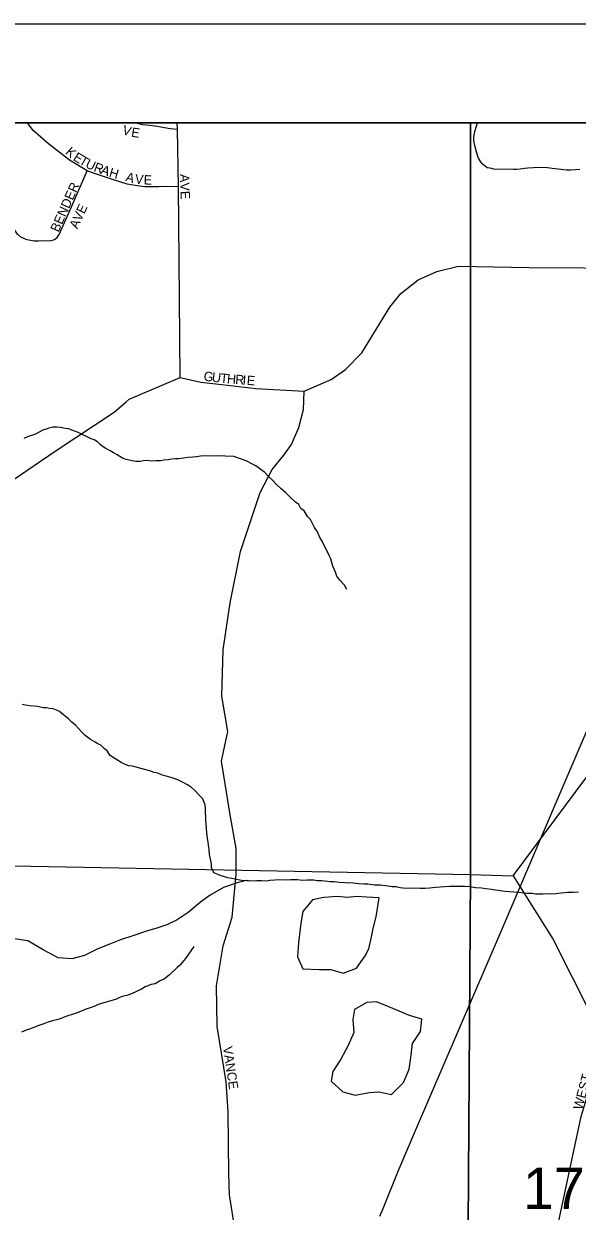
# Model space of a CAD drawing. Extents: x -209 to 4852, y 0 to 905.
# Drawn here: x 494.13 to 505.3, y 316.6 to 340.56 of the extents above; entities that cross this region are included whole.
import ezdxf

# ---------------------------------------------------------------- set-up
doc = ezdxf.new("R2010")
doc.units = 0
for name, color, linetype in [('Default', 7, 'Continuous'), ('GM_X_Airport_Location_Class_2', 7, 'Continuous'), ('GM_X_Airport_Location_Class_3', 7, 'Continuous'), ('GM_X_County_Road', 7, 'Continuous'), ('GM_X_Major_River', 7, 'Continuous'), ('GM_X_Minor_Lake_Text', 7, 'Continuous'), ('GM_X_Minor_River', 7, 'Continuous'), ('GM_X_Township_Road_Text', 7, 'Continuous'), ('GM_X_US_Location', 7, 'Continuous'), ('GM_X_US_Route', 7, 'Continuous'), ('SH_Data', 7, 'Continuous')]:
    doc.layers.add(name, color=color, linetype=linetype)

msp = doc.modelspace()

# ---------------------------------------------------------------- linework, layer by layer
at = {"layer": 'Default'}
msp.add_lwpolyline([(571.768, 202.559), (571.768, 338.559), (435.768, 338.559), (435.768, 202.559)], close=True, dxfattribs=at)
at = {"layer": 'GM_X_Airport_Location_Class_2'}
for points in [[(494.16, 336.213), (494.067, 336.252), (494.003, 336.316), (493.899, 336.464), (493.805, 336.75), (493.677, 337.045), (493.559, 337.213), (492.909, 338.08), (492.597, 338.559)], [(495.514, 337.552), (495.408, 337.589), (495.05, 337.81), (494.623, 338.137), (494.318, 338.404), (494.205, 338.559)], [(497.227, 338.429), (497.084, 338.438), (496.965, 338.459), (496.82, 338.485), (496.67, 338.505), (496.525, 338.521), (496.362, 338.559)], [(497.286, 333.423), (497.273, 335.023), (497.25, 337.271), (497.227, 338.429), (497.226, 338.559)], [(494.841, 336.307), (495.088, 336.865), (495.408, 337.589)], [(497.25, 337.271), (497.008, 337.277), (496.855, 337.269), (496.665, 337.269), (496.573, 337.269), (496.413, 337.292), (496.215, 337.322), (495.918, 337.414), (495.514, 337.552)], [(494.16, 336.213), (494.339, 336.181), (494.425, 336.181), (494.526, 336.184), (494.657, 336.181), (494.748, 336.209), (494.803, 336.244), (494.841, 336.307)], [(499.786, 333.145), (499.786, 333.145), (500.334, 333.382), (500.624, 333.587), (500.947, 333.923), (501.514, 334.839), (501.736, 335.116), (502.086, 335.394), (502.464, 335.564), (502.903, 335.668), (504.329, 335.64), (506.529, 335.63), (506.737, 335.574), (506.888, 335.489), (507.148, 335.253), (507.852, 334.299), (507.902, 334.336)], [(496.191, 332.931), (496.254, 332.986), (496.651, 333.156), (497.286, 333.423)], [(497.286, 333.423), (497.701, 333.331), (498.123, 333.279), (498.812, 333.204), (499.786, 333.145)], [(498.395, 316.207), (498.277, 316.932), (498.263, 317.361), (498.251, 318.606), (498.211, 319.213), (498.033, 320.331), (498.019, 321.152), (498.151, 321.956), (498.336, 322.536), (498.413, 323.401), (498.413, 323.923), (498.283, 324.64), (498.12, 325.684), (498.244, 326.281), (498.125, 326.993), (498.151, 327.93), (498.296, 328.879), (498.501, 329.914), (498.896, 331.101), (499.14, 331.569), (499.378, 331.853), (499.529, 332.07), (499.681, 332.413), (499.773, 332.776), (499.786, 333.145)], [(483.392, 325.722), (489.662, 325.638), (489.945, 325.638), (490.059, 325.714), (490.153, 325.846), (490.191, 326.111), (490.153, 327.49), (490.172, 327.546), (490.172, 327.565), (490.191, 327.678), (490.267, 327.811), (490.474, 328.037), (491.74, 328.906), (492.477, 329.378), (492.722, 329.548), (492.911, 329.737), (493.005, 329.926), (493.194, 330.455), (493.326, 330.814), (493.326, 330.833), (493.61, 331.154), (494.781, 331.947), (495.952, 332.722), (496.191, 332.931)], [(503.856, 313.234), (504.046, 313.362), (504.197, 313.663), (504.53, 314.568), (504.788, 315.633), (504.917, 316.375), (505.38, 318.516), (505.961, 320.453), (506.267, 321.322), (506.357, 321.685), (506.469, 322.321), (506.657, 323.59), (507.46, 326.374), (508.038, 328.172), (508.092, 328.334)]]:
    msp.add_lwpolyline(points, dxfattribs=at)
at = {"layer": 'GM_X_County_Road'}
for points in [[(505.349, 337.621), (505.265, 337.615), (505.166, 337.602), (505.082, 337.605), (504.916, 337.624), (504.794, 337.642), (504.696, 337.652), (504.521, 337.656), (504.414, 337.651), (504.3, 337.647), (504.231, 337.641), (504.147, 337.628), (504.071, 337.622), (504.01, 337.616), (503.615, 337.626), (503.539, 337.643), (503.479, 337.652), (503.382, 337.73), (503.338, 337.792), (503.301, 337.861), (503.266, 337.976), (503.231, 338.106), (503.211, 338.198), (503.213, 338.274), (503.231, 338.388), (503.287, 338.559)], [(500.645, 329.147), (500.602, 329.232), (500.506, 329.333), (500.447, 329.418), (500.418, 329.495), (500.368, 329.617), (500.326, 329.763), (500.29, 329.832), (500.239, 329.948), (500.195, 330.017), (500.152, 330.124), (500.101, 330.194), (500.058, 330.309), (499.992, 330.395), (499.912, 330.556), (499.853, 330.618), (499.787, 330.734), (499.72, 330.781), (499.676, 330.858), (499.609, 330.906), (499.505, 331.007), (499.408, 331.101), (499.319, 331.179), (499.23, 331.265), (499.148, 331.35), (499.074, 331.421), (498.992, 331.506), (498.917, 331.561), (498.813, 331.64), (498.745, 331.672), (498.618, 331.744), (498.52, 331.776), (498.369, 331.826), (498.194, 331.838), (498.034, 331.842), (497.928, 331.837), (497.791, 331.84), (497.692, 331.835), (497.616, 331.822), (497.539, 331.816), (497.44, 331.811), (497.349, 331.798), (497.25, 331.785), (497.189, 331.779), (497.112, 331.773), (497.044, 331.76), (496.952, 331.754), (496.891, 331.741), (496.8, 331.743), (496.708, 331.738), (496.617, 331.747), (496.541, 331.742), (496.48, 331.728), (496.389, 331.73), (496.283, 331.748), (496.192, 331.766), (496.117, 331.798), (496.012, 331.861), (495.937, 331.901), (495.869, 331.941), (495.772, 331.996), (495.675, 332.067), (495.615, 332.122), (495.548, 332.162), (495.487, 332.186), (495.382, 332.242), (495.292, 332.282), (495.209, 332.322), (495.096, 332.363), (495.036, 332.387), (494.968, 332.396), (494.869, 332.414), (494.793, 332.423), (494.717, 332.418), (494.656, 332.404), (494.579, 332.383), (494.51, 332.362), (494.426, 332.311), (494.364, 332.282), (494.303, 332.261), (494.203, 332.225), (494.126, 332.189)], [(498.243, 323.33), (498.092, 323.379), (498.032, 323.403), (497.964, 323.428), (497.914, 323.536), (497.915, 323.604), (497.902, 323.68), (497.875, 323.803), (497.87, 323.902), (497.856, 323.986), (497.85, 324.054), (497.837, 324.123), (497.825, 324.237), (497.812, 324.329), (497.806, 324.42), (497.8, 324.489), (497.802, 324.565), (497.796, 324.626), (497.798, 324.724), (497.785, 324.793), (497.743, 324.923), (497.683, 324.986), (497.572, 325.095), (497.512, 325.15), (497.43, 325.205), (497.332, 325.26), (497.235, 325.309), (497.144, 325.341), (497.076, 325.358), (497.001, 325.383), (496.91, 325.408), (496.835, 325.44), (496.759, 325.457), (496.669, 325.49), (496.518, 325.531), (496.397, 325.565), (496.314, 325.582), (496.245, 325.591), (496.163, 325.624), (496.095, 325.656), (496.02, 325.703), (495.952, 325.743), (495.863, 325.806), (495.819, 325.883), (495.759, 325.93), (495.685, 326.008), (495.625, 326.032), (495.565, 326.064), (495.475, 326.12), (495.363, 326.199), (495.296, 326.269), (495.229, 326.339), (495.17, 326.409), (495.096, 326.471), (495.029, 326.534), (494.932, 326.62), (494.85, 326.683), (494.79, 326.714), (494.722, 326.739), (494.646, 326.748), (494.578, 326.758), (494.517, 326.759), (494.404, 326.785), (494.252, 326.796), (494.161, 326.814), (494.093, 326.823)], [(498.713, 323.265), (498.625, 323.275), (498.434, 323.225), (498.159, 323.132), (497.891, 322.977), (497.691, 322.837), (497.444, 322.629), (497.221, 322.481), (497.014, 322.379), (496.815, 322.314), (496.602, 322.25), (496.35, 322.163), (496.082, 322.077), (495.876, 321.998), (495.624, 321.896), (495.356, 321.764), (495.096, 321.693), (494.823, 321.714), (494.516, 321.879), (494.208, 322.06), (493.943, 322.096)], [(505.325, 323.041), (505.218, 323.036), (505.104, 323.031), (505.043, 323.025), (504.975, 323.019), (504.875, 323.006), (504.784, 323.001), (504.7, 323.003), (504.601, 322.998), (504.525, 323), (504.457, 323.001), (504.389, 323.011), (504.282, 323.013), (504.214, 323.023), (504.123, 323.032), (504.017, 323.043), (503.842, 323.055), (503.751, 323.064), (503.645, 323.082), (503.569, 323.092), (503.456, 323.11), (503.365, 323.12), (503.243, 323.13), (503.137, 323.148), (503.023, 323.151), (502.917, 323.153), (502.818, 323.156), (502.726, 323.151), (502.429, 323.135), (502.323, 323.123), (502.224, 323.117), (502.132, 323.112), (501.783, 323.121), (501.722, 323.13), (501.646, 323.147), (501.563, 323.149), (501.479, 323.159), (501.32, 323.178), (501.206, 323.181), (501.07, 323.199), (500.994, 323.201), (500.88, 323.211), (500.773, 323.222), (500.614, 323.226), (500.492, 323.236), (500.401, 323.246), (500.31, 323.248), (500.204, 323.259), (500.136, 323.268), (500.052, 323.27), (499.984, 323.279), (499.855, 323.282), (499.756, 323.277), (499.649, 323.287), (499.513, 323.291), (499.452, 323.285), (499.292, 323.289), (499.094, 323.278), (499.025, 323.265), (498.926, 323.267), (498.828, 323.27), (498.713, 323.265), (498.63, 323.267), (498.531, 323.277), (498.448, 323.287), (498.387, 323.303), (498.327, 323.313), (498.243, 323.33)], [(497.295, 321.582), (497.395, 321.702), (497.567, 321.942)], [(497.295, 321.582), (497.225, 321.523), (497.062, 321.367), (496.969, 321.294), (496.869, 321.243), (496.776, 321.192), (496.7, 321.179), (496.577, 321.128), (496.5, 321.085), (496.3, 320.991), (496.207, 320.955), (496.139, 320.942), (496.062, 320.913), (496, 320.884), (495.632, 320.772), (495.563, 320.743), (495.487, 320.714), (495.387, 320.679), (495.302, 320.643), (495.225, 320.614), (495.103, 320.572), (495.018, 320.543), (494.942, 320.515), (494.88, 320.494), (494.796, 320.465), (494.704, 320.445), (494.597, 320.409), (494.535, 320.381), (494.428, 320.353), (494.313, 320.302), (494.243, 320.274), (494.175, 320.253), (494.082, 320.217)]]:
    msp.add_lwpolyline(points, dxfattribs=at)
at = {"layer": 'GM_X_Major_River'}
for points in [[(501.297, 322.927), (501.046, 322.939), (500.849, 322.95), (500.659, 322.931), (500.462, 322.95), (500.181, 322.933), (499.953, 322.884), (499.758, 322.652), (499.724, 322.455), (499.698, 322.25), (499.67, 322.015), (499.65, 321.734), (499.759, 321.496), (500.092, 321.482), (500.327, 321.478), (500.576, 321.404), (500.844, 321.506), (501.016, 321.753)], [(501.016, 321.753), (501.094, 321.896), (501.136, 322.108), (501.178, 322.305), (501.243, 322.54), (501.297, 322.927)], [(501.496, 320.725), (501.248, 320.829), (501.051, 320.817), (500.805, 320.67), (500.771, 320.473), (500.788, 320.206), (500.677, 319.95), (500.527, 319.672), (500.363, 319.424), (500.329, 319.227), (500.568, 319.009), (500.817, 318.943), (501.106, 318.999), (501.296, 319.01), (501.546, 318.96), (501.793, 319.198), (501.905, 319.47)], [(501.905, 319.47), (501.939, 319.705), (501.975, 319.986), (502.132, 320.226), (502.159, 320.476), (501.91, 320.55), (501.496, 320.725)]]:
    msp.add_lwpolyline(points, dxfattribs=at)
at = {"layer": 'GM_X_Minor_Lake_Text'}
msp.add_lwpolyline([(514.904, 338.559), (483.334, 338.559), (483.392, 325.723), (483.369, 322.855), (483.249, 313.713), (483.171, 310.029), (483.074, 303.486), (482.984, 295.952), (482.84, 285.356)], dxfattribs=at)
at = {"layer": 'GM_X_Minor_River'}
for points in [[(503.146, 338.559), (483.207, 338.559), (483.256, 323.774), (503.144, 323.396)], [(514.348, 338.559), (503.146, 338.559), (503.144, 323.396), (504.007, 323.372), (505.686, 325.628), (507.263, 328.166), (508.201, 330.11), (509.524, 332.419), (511.394, 334.77), (513.318, 336.779)], [(483.256, 323.774), (503.144, 323.396), (503.056, 310.202), (502.765, 309.61), (502.156, 308.265), (501.547, 306.481), (500.992, 304.719), (500.816, 303.404), (483.023, 303.524), (483.246, 322.903)], [(503.144, 323.396), (504.007, 323.372), (504.809, 322.084), (505.956, 319.821), (506.865, 318.236), (506.647, 316.293), (506.296, 314.944), (505.386, 313.673), (504.418, 312.131), (503.056, 310.202)]]:
    msp.add_lwpolyline(points, close=True, dxfattribs=at)
at = {"layer": 'GM_X_US_Location'}
msp.add_lwpolyline([(515.21, 338.559), (475.437, 338.559)], dxfattribs=at)
msp.add_lwpolyline([(515.21, 338.559), (475.437, 338.559)], dxfattribs=at)
at = {"layer": 'GM_X_US_Route'}
msp.add_lwpolyline([(501.317, 316.503), (501.379, 316.657), (501.686, 317.412), (502.031, 318.229), (503.771, 322.27), (504.93, 324.99), (506.153, 327.828)], dxfattribs=at)
at = {"layer": 'SH_Data'}
for p, q in [((433.768, 340.559), (573.768, 340.559)), ((435.768, 338.559), (571.768, 338.559))]:
    msp.add_line(p, q, dxfattribs=at)

# ---------------------------------------------------------------- texts
at = {"layer": 'GM_X_Airport_Location_Class_3'}
for s, height, rotation, p in [('V', 0.189, 343.6244, (496.102, 338.336)), ('E', 0.189, 350.8438, (496.287, 338.283)), ('K', 0.189, 318.0307, (494.955, 337.951)), ('E', 0.189, 328.3974, (495.109, 337.817)), ('T', 0.189, 329.7623, (495.227, 337.744)), ('U', 0.189, 334.5434, (495.357, 337.669)), ('R', 0.189, 339.915, (495.526, 337.59)), ('A', 0.189, 339.9693, (495.667, 337.538)), ('H', 0.189, 343.6244, (495.836, 337.477)), ('A', 0.189, 344.3519, (496.17, 337.389)), ('BENDER', 0.1894, 66.1408, (494.829, 336.341)), ('V', 0.189, 353.5709, (496.363, 337.338)), ('E', 0.189, 358.1599, (496.545, 337.318)), ('A', 0.189, 270.1093, (497.28, 337.527)), ('V', 0.189, 272.0332, (497.281, 337.353)), ('E', 0.189, 273.7302, (497.287, 337.181)), ('E', 0.189, 64.3147, (495.347, 336.71)), ('V', 0.189, 65.4294, (495.278, 336.56)), ('A', 0.189, 65.7423, (495.209, 336.408)), ('G', 0.189, 352.6148, (497.749, 333.362)), ('U', 0.189, 352.7454, (497.915, 333.341)), ('T', 0.189, 354.3645, (498.086, 333.319)), ('H', 0.189, 355.5224, (498.223, 333.306)), ('R', 0.189, 355.6165, (498.39, 333.293)), ('I', 0.189, 355.6248, (498.539, 333.281)), ('E', 0.189, 355.5971, (498.622, 333.275)), ('VANCE', 0.1894, 278.2949, (498.147, 319.915)), ('WEST', 0.1894, 74.8794, (505.394, 318.636))]:
    msp.add_text(s, height=height, rotation=rotation, dxfattribs=at).set_placement(p)
at = {"layer": 'GM_X_Township_Road_Text'}
msp.add_text('17', height=0.8371, rotation=0, dxfattribs=at).set_placement((504.203, 316.647))

doc.saveas('drawing.dxf')
